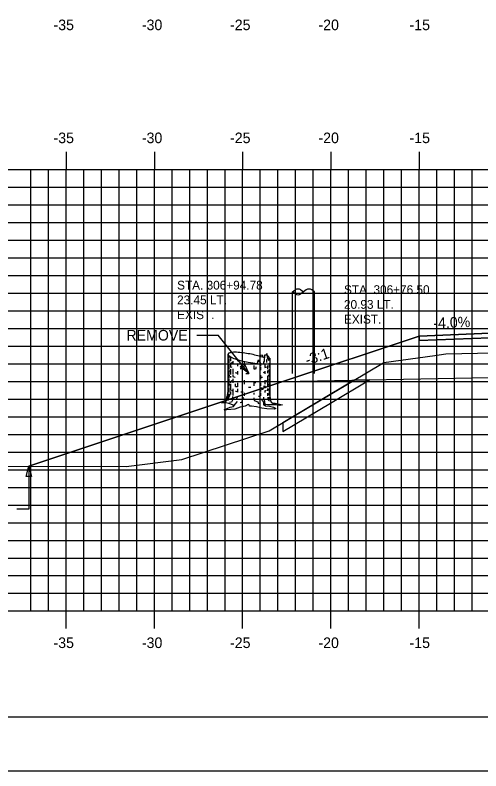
# Model space of a CAD drawing. Extents: x 1137654 to 1137824, y 608981 to 609091.
# Drawn here: x 1137699.51 to 1137725.91, y 608981.28 to 609024.09 of the extents above; entities that cross this region are included whole.
import ezdxf

# ---------------------------------------------------------------- set-up
doc = ezdxf.new("R2010")
doc.units = 0
for name, color, linetype in [('ANNOTATION', 7, 'Continuous'), ('BORDER', 7, 'Continuous'), ('D_Roadway_Edge_Shoulder', 7, 'Continuous'), ('D_Roadway_SlopeLines', 7, 'Continuous'), ('D_Roadway_SubGrade', 7, 'Continuous'), ('D_Text_Monospaced', 7, 'Continuous'), ('D_Text_Standard', 7, 'Continuous'), ('H_V ANNOTATION', 7, 'Continuous'), ('MAJOR', 7, 'Continuous'), ('MINOR', 7, 'Continuous'), ('PLOT BOUNDARY', 7, 'Continuous'), ('S_Roadway_Centerline', 7, 'Continuous'), ('S_Trees_Decid_Pay', 7, 'Continuous'), ('S_Utilities_Pole_Power', 7, 'Continuous'), ('SHADING', 7, 'Continuous')]:
    doc.layers.add(name, color=color, linetype=linetype)

msp = doc.modelspace()

# ---------------------------------------------------------------- linework, layer by layer
msp.add_lwpolyline([(1137700.29, 608998.532), (1137711.685, 609002.33), (1137714.685, 609003.33), (1137722.408, 609005.904), (1137722.409, 609005.904), (1137726.409, 609006.064), (1137737.409, 609006.284), (1137748.409, 609006.504), (1137752.409, 609006.344), (1137760.133, 609003.77), (1137763.133, 609002.77), (1137763.471, 609002.657)])
at = {"layer": 'ANNOTATION'}
for p in [(1137709.813, 609005.955), (1137712.756, 609003.786)]:
    msp.add_line(p, (1137711.013, 609005.955), dxfattribs=at)
msp.add_lwpolyline([(1137712.497, 609004.348), (1137712.756, 609003.786), (1137712.263, 609004.16)], close=True, dxfattribs=at)
at = {"layer": 'BORDER'}
msp.add_lwpolyline([(1137662.41, 608984.335), (1137822.41, 608984.335), (1137822.41, 609089.335), (1137662.41, 609089.335)], close=True, dxfattribs=at)
at = {"layer": 'D_Roadway_Edge_Shoulder'}
msp.add_lwpolyline([(1137726.409, 609006.064), (1137722.409, 609005.904), (1137722.409, 609005.654), (1137726.409, 609005.814)], close=True, dxfattribs=at)
at = {"layer": 'D_Roadway_SlopeLines'}
for points in [[(1137714.685, 609003.33), (1137711.685, 609002.33)], [(1137714.685, 609000.999), (1137714.685, 609000.499), (1137717.38, 609002.105), (1137719.599, 609003.428)], [(1137711.685, 609002.33), (1137700.29, 608998.532)]]:
    msp.add_lwpolyline(points, dxfattribs=at)
at = {"layer": 'D_Roadway_SubGrade'}
msp.add_lwpolyline([(1137726.409, 609005.648), (1137726.409, 609005.814), (1137722.409, 609005.654), (1137722.409, 609005.904), (1137722.408, 609005.904), (1137714.685, 609003.33), (1137726.409, 609003.564)], close=True, dxfattribs=at)
at = {"layer": 'D_Text_Standard'}
msp.add_lwpolyline([(1137700.29, 608998.532), (1137700.3, 608996.105), (1137699.62, 608996.105)], dxfattribs=at)
msp.add_lwpolyline([(1137700.29, 608998.532), (1137700.438, 608997.95), (1137700.147, 608997.949)], close=True, dxfattribs=at)
at = {"layer": 'MAJOR'}
for p, q in [((1137702.409, 609016.337), (1137702.409, 609015.335)), ((1137707.409, 609016.337), (1137707.409, 609015.335)), ((1137712.409, 609016.337), (1137712.409, 609015.335)), ((1137717.409, 609016.337), (1137717.409, 609015.335)), ((1137722.409, 609016.337), (1137722.409, 609015.335)), ((1137667.409, 609015.335), (1137807.409, 609015.335)), ((1137667.409, 609015.335), (1137807.409, 609015.335)), ((1137702.409, 608990.335), (1137702.409, 609015.335)), ((1137707.409, 608990.335), (1137707.409, 609015.335)), ((1137712.409, 608990.335), (1137712.409, 609015.335)), ((1137717.409, 608990.335), (1137717.409, 609015.335)), ((1137722.409, 608990.335), (1137722.409, 609015.335)), ((1137667.409, 609010.335), (1137807.409, 609010.335)), ((1137667.409, 609005.335), (1137807.409, 609005.335)), ((1137667.409, 609000.335), (1137807.409, 609000.335)), ((1137667.409, 608995.335), (1137807.409, 608995.335)), ((1137667.409, 608990.335), (1137807.409, 608990.335)), ((1137667.409, 608990.335), (1137807.409, 608990.335)), ((1137702.409, 608989.333), (1137702.409, 608990.335)), ((1137707.409, 608989.333), (1137707.409, 608990.335)), ((1137712.409, 608989.333), (1137712.409, 608990.335)), ((1137717.409, 608989.333), (1137717.409, 608990.335)), ((1137722.409, 608989.333), (1137722.409, 608990.335))]:
    msp.add_line(p, q, dxfattribs=at)
at = {"layer": 'MINOR'}
for p, q in [((1137700.409, 608990.335), (1137700.409, 609015.335)), ((1137701.409, 608990.335), (1137701.409, 609015.335)), ((1137703.409, 608990.335), (1137703.409, 609015.335)), ((1137704.409, 608990.335), (1137704.409, 609015.335)), ((1137705.409, 608990.335), (1137705.409, 609015.335)), ((1137706.409, 608990.335), (1137706.409, 609015.335)), ((1137708.409, 608990.335), (1137708.409, 609015.335)), ((1137709.409, 608990.335), (1137709.409, 609015.335)), ((1137710.409, 608990.335), (1137710.409, 609015.335)), ((1137711.409, 608990.335), (1137711.409, 609015.335)), ((1137713.409, 608990.335), (1137713.409, 609015.335)), ((1137714.409, 608990.335), (1137714.409, 609015.335)), ((1137715.409, 608990.335), (1137715.409, 609015.335)), ((1137716.409, 608990.335), (1137716.409, 609015.335)), ((1137718.409, 608990.335), (1137718.409, 609015.335)), ((1137719.409, 608990.335), (1137719.409, 609015.335)), ((1137720.409, 608990.335), (1137720.409, 609015.335)), ((1137721.409, 608990.335), (1137721.409, 609015.335)), ((1137723.409, 608990.335), (1137723.409, 609015.335)), ((1137724.409, 608990.335), (1137724.409, 609015.335)), ((1137725.409, 608990.335), (1137725.409, 609015.335)), ((1137667.409, 609014.335), (1137807.409, 609014.335)), ((1137667.409, 609013.335), (1137807.409, 609013.335)), ((1137667.409, 609012.335), (1137807.409, 609012.335)), ((1137667.409, 609011.335), (1137807.409, 609011.335)), ((1137667.409, 609009.335), (1137807.409, 609009.335)), ((1137667.409, 609008.335), (1137807.409, 609008.335)), ((1137667.409, 609007.335), (1137807.409, 609007.335)), ((1137667.409, 609006.335), (1137807.409, 609006.335)), ((1137667.409, 609004.335), (1137807.409, 609004.335)), ((1137667.409, 609003.335), (1137807.409, 609003.335)), ((1137667.409, 609002.335), (1137807.409, 609002.335)), ((1137667.409, 609001.335), (1137807.409, 609001.335)), ((1137667.409, 608999.335), (1137807.409, 608999.335)), ((1137667.409, 608998.335), (1137807.409, 608998.335)), ((1137667.409, 608997.335), (1137807.409, 608997.335)), ((1137667.409, 608996.335), (1137807.409, 608996.335)), ((1137667.409, 608994.335), (1137807.409, 608994.335)), ((1137667.409, 608993.335), (1137807.409, 608993.335)), ((1137667.409, 608992.335), (1137807.409, 608992.335)), ((1137667.409, 608991.335), (1137807.409, 608991.335))]:
    msp.add_line(p, q, dxfattribs=at)
at = {"layer": 'PLOT BOUNDARY'}
msp.add_lwpolyline([(1137654.316, 608981.276), (1137824.316, 608981.276), (1137824.316, 609091.276), (1137654.316, 609091.276)], close=True, dxfattribs=at)
at = {"layer": 'S_Roadway_Centerline'}
msp.add_lwpolyline([(1137667.409, 608999.427), (1137671.375, 608999.533), (1137682.176, 608998.539), (1137682.929, 608998.559), (1137705.808, 608998.523), (1137708.965, 608998.916), (1137713.914, 609000.539), (1137720.407, 609004.41), (1137723.296, 609004.805), (1137723.932, 609004.904), (1137726.625, 609004.961), (1137735.098, 609005.026), (1137742.791, 609004.952), (1137745.524, 609004.989), (1137745.621, 609004.875), (1137747.251, 609004.35), (1137748.161, 609004.238), (1137757.699, 609001.458), (1137758.717, 609001.317), (1137759.74, 609001.407), (1137760.775, 609001.568), (1137762.91, 609002.502), (1137768.911, 609004.157)], dxfattribs=at)
at = {"layer": 'S_Trees_Decid_Pay'}
for p, q in [((1137711.632, 609004.785), (1137711.632, 609004.664)), ((1137711.712, 609004.74), (1137711.712, 609004.487)), ((1137711.632, 609004.612), (1137711.632, 609004.398)), ((1137711.632, 609004.353), (1137711.632, 609004.015)), ((1137711.712, 609004.391), (1137711.712, 609004.127)), ((1137711.845, 609004.487), (1137711.845, 609004.295)), ((1137712.117, 609004.574), (1137712.117, 609004.487)), ((1137712.117, 609004.346), (1137712.117, 609004.207)), ((1137712.5, 609004.473), (1137712.5, 609004.192)), ((1137713.411, 609004.335), (1137713.411, 609004.215)), ((1137713.672, 609004.333), (1137713.672, 609004.128)), ((1137713.757, 609004.581), (1137713.757, 609004.407)), ((1137713.906, 609004.381), (1137713.906, 609004.127)), ((1137711.632, 609003.898), (1137711.632, 609003.538)), ((1137711.712, 609004.03), (1137711.712, 609003.721)), ((1137711.845, 609004.044), (1137711.845, 609003.767)), ((1137712.117, 609003.921), (1137712.117, 609003.729)), ((1137712.5, 609004.127), (1137712.5, 609004.024)), ((1137713.046, 609004.236), (1137713.046, 609004.056)), ((1137713.173, 609004.063), (1137713.168, 609004.17)), ((1137713.411, 609004.164), (1137713.411, 609003.978)), ((1137713.672, 609003.921), (1137713.672, 609003.767)), ((1137713.82, 609004.236), (1137713.82, 609004.024)), ((1137713.82, 609003.958), (1137713.82, 609003.81)), ((1137713.906, 609004.03), (1137713.906, 609003.56)), ((1137711.632, 609003.501), (1137711.632, 609003.052)), ((1137711.712, 609003.633), (1137711.712, 609003.566)), ((1137711.845, 609003.721), (1137711.845, 609003.612)), ((1137711.845, 609003.478), (1137711.845, 609003.249)), ((1137713.411, 609003.692), (1137713.411, 609003.464)), ((1137713.82, 609003.633), (1137713.82, 609003.332)), ((1137713.906, 609003.509), (1137713.906, 609003.375)), ((1137711.712, 609003.332), (1137711.712, 609003.235)), ((1137711.712, 609003.184), (1137711.712, 609002.824)), ((1137712.117, 609003.249), (1137712.117, 609003.041)), ((1137712.5, 609003.412), (1137712.5, 609003.192)), ((1137713.046, 609003.278), (1137713.046, 609003.081)), ((1137713.411, 609003.266), (1137713.411, 609003.081)), ((1137713.672, 609003.404), (1137713.672, 609003.184)), ((1137713.672, 609003.084), (1137713.672, 609002.963)), ((1137713.82, 609003.295), (1137713.82, 609003.052)), ((1137713.906, 609003.318), (1137713.906, 609002.992)), ((1137711.632, 609002.986), (1137711.632, 609002.704)), ((1137711.712, 609002.772), (1137711.712, 609002.605)), ((1137711.845, 609002.92), (1137711.845, 609002.537)), ((1137712.117, 609002.92), (1137712.117, 609002.721)), ((1137712.5, 609002.692), (1137712.5, 609002.518)), ((1137713.046, 609002.698), (1137713.046, 609002.595)), ((1137713.411, 609002.846), (1137713.411, 609002.769)), ((1137713.411, 609002.692), (1137713.411, 609002.518)), ((1137713.672, 609002.812), (1137713.672, 609002.714)), ((1137713.82, 609002.941), (1137713.82, 609002.801)), ((1137713.82, 609002.669), (1137713.82, 609002.513)), ((1137713.906, 609002.963), (1137713.906, 609002.543)), ((1137712.122, 609002.463), (1137712.042, 609002.331)), ((1137713.903, 609002.44), (1137713.918, 609002.323))]:
    msp.add_line(p, q, dxfattribs=at)
for points in [[(1137713.957, 609004.656), (1137713.957, 609002.518), (1137713.977, 609002.377), (1137713.983, 609002.251), (1137714.026, 609002.164), (1137714.119, 609002.115), (1137714.255, 609002.115), (1137714.498, 609002.059), (1137714.665, 609002.01), (1137714.522, 609001.979), (1137714.286, 609002.017), (1137714.076, 609002.004), (1137713.814, 609002.01), (1137713.69, 609002.028), (1137713.66, 609001.986), (1137713.598, 609002.028), (1137713.697, 609001.961), (1137713.932, 609001.936), (1137714.162, 609001.874), (1137714.292, 609001.804), (1137714.193, 609001.761), (1137713.771, 609001.78), (1137713.493, 609001.823), (1137713.194, 609001.899), (1137712.908, 609001.936), (1137712.803, 609001.936), (1137712.785, 609002.017), (1137712.717, 609002.022), (1137712.55, 609001.936), (1137712.264, 609001.88), (1137711.965, 609001.773), (1137711.506, 609001.724), (1137711.352, 609001.736), (1137711.694, 609001.887), (1137711.897, 609001.917), (1137711.885, 609001.992), (1137711.626, 609002.091), (1137711.45, 609002.122), (1137711.21, 609002.133), (1137711.408, 609002.171), (1137711.469, 609002.207), (1137711.494, 609002.294), (1137711.506, 609002.463), (1137711.551, 609002.549), (1137711.58, 609002.79), (1137711.58, 609004.876)], [(1137713.578, 609004.694), (1137713.557, 609004.802), (1137713.425, 609004.833), (1137713.418, 609004.745)], [(1137713.601, 609004.328), (1137713.608, 609004.473), (1137713.654, 609004.465), (1137713.668, 609004.839), (1137713.763, 609004.847), (1137713.777, 609004.927), (1137713.814, 609004.59), (1137713.86, 609004.685), (1137713.88, 609004.53), (1137713.957, 609004.656), (1137713.951, 609004.466)], [(1137713.957, 609004.656), (1137713.911, 609004.679), (1137713.889, 609004.744), (1137713.837, 609004.767), (1137713.803, 609004.692)], [(1137713.439, 609004.333), (1137713.402, 609004.436), (1137713.337, 609004.442), (1137713.337, 609004.524), (1137713.263, 609004.53), (1137713.238, 609004.35)], [(1137712.003, 609003.055), (1137712.005, 609003.132), (1137712.013, 609003.198)], [(1137711.63, 609002.632), (1137711.57, 609002.471), (1137711.556, 609002.346), (1137711.564, 609002.249)], [(1137713.549, 609002.963), (1137713.557, 609002.889), (1137713.483, 609002.883), (1137713.469, 609003)], [(1137711.687, 609002.551), (1137711.616, 609002.448), (1137711.616, 609002.323)], [(1137711.828, 609002.477), (1137711.828, 609002.272), (1137711.77, 609002.162), (1137711.673, 609002.146)], [(1137711.897, 609001.917), (1137711.984, 609002.059), (1137712.116, 609002.202)], [(1137712.482, 609002.403), (1137712.379, 609002.352), (1137712.365, 609002.146), (1137712.262, 609002.117)], [(1137713.048, 609002.412), (1137713.065, 609002.257), (1137713.263, 609002.177), (1137713.308, 609002.074)], [(1137713.5, 609002.276), (1137713.574, 609002.207), (1137713.592, 609002.109), (1137713.598, 609002.028)], [(1137713.69, 609002.028), (1137713.672, 609002.207), (1137713.61, 609002.344), (1137713.617, 609002.444)], [(1137713.837, 609002.448), (1137713.843, 609002.323), (1137713.925, 609002.228)]]:
    msp.add_lwpolyline(points, dxfattribs=at)
for centre, radius, start, end in [((1137711.626, 609004.876), 0.0467, 169.2221, 180.9043), ((1137711.634, 609004.876), 0.0544, 180.9043, 191.7221), ((1137711.626, 609004.876), 0.0467, 157.54, 169.2221), ((1137711.644, 609004.878), 0.0645, 191.7221, 204.3989), ((1137711.633, 609004.873), 0.0544, 146.7221, 157.54), ((1137711.683, 609004.896), 0.107, 204.3989, 214.2221), ((1137711.642, 609004.868), 0.0645, 134.0453, 146.7221), ((1137711.73, 609004.928), 0.164, 214.2221, 228.4286), ((1137711.671, 609004.837), 0.107, 124.2221, 134.0453), ((1137711.703, 609004.79), 0.164, 110.0157, 124.2221), ((1137711.939, 609005.164), 0.48, 228.4286, 236.7221), ((1137711.811, 609004.494), 0.48, 101.7221, 110.0157), ((1137712.389, 609005.85), 1.299, 236.7221, 252.1387), ((1137711.978, 609003.691), 1.299, 86.3056, 101.7221), ((1137711.667, 608998.875), 6.126, 79.2221, 86.3056), ((1137711.667, 608998.875), 6.126, 72.1387, 79.2221), ((1137711.634, 609004.55), 0.0554, 191.6815, 202.5), ((1137711.643, 609004.554), 0.0657, 202.5, 215.1737), ((1137711.679, 609004.579), 0.109, 215.1737, 225), ((1137711.719, 609004.619), 0.166, 225, 238.33), ((1137712.191, 609005.638), 1.292, 250.9084, 254.4349), ((1137713.869, 609010.443), 6.126, 252.1387, 259.2221), ((1137712.767, 609010.226), 5.916, 263.6913, 265.0485), ((1137713.869, 609010.443), 6.126, 259.2221, 264.0853), ((1137713.869, 609010.443), 6.126, 265.9754, 266.3056), ((1137713.558, 609005.627), 1.299, 266.3056, 271.8711), ((1137713.147, 609003.468), 1.299, 66.6931, 72.1387), ((1137711.635, 609004.289), 0.0554, 191.6815, 202.5), ((1137711.644, 609004.293), 0.0657, 202.5, 215.1737), ((1137711.68, 609004.318), 0.109, 215.1737, 225), ((1137711.72, 609004.358), 0.166, 225, 239.1924), ((1137711.72, 609004.095), 0.166, 238.3999, 239.1924), ((1137711.883, 609004.631), 0.484, 239.1924, 242.5838), ((1137711.883, 609004.368), 0.484, 239.1924, 247.5), ((1137712.192, 609005.378), 1.292, 247.5, 251.9171), ((1137712.192, 609005.114), 1.292, 247.5, 248.1929), ((1137712.768, 609009.966), 5.916, 265.1076, 266.4618), ((1137712.768, 609009.966), 5.916, 272.6957, 273.9224), ((1137713.344, 609005.378), 1.292, 284.7144, 289.3881), ((1137713.344, 609005.114), 1.292, 291.6463, 292.5), ((1137713.653, 609004.368), 0.484, 292.5, 300.8076), ((1137713.816, 609004.358), 0.166, 300.8076, 315), ((1137713.816, 609004.095), 0.166, 300.8076, 302.9622), ((1137713.856, 609004.318), 0.109, 315, 324.8263), ((1137713.892, 609004.293), 0.0657, 324.8263, 337.5), ((1137713.901, 609004.289), 0.0554, 337.5, 348.3185), ((1137713.909, 609004.287), 0.0476, 348.3185, 0), ((1137711.635, 609003.768), 0.0554, 191.6815, 202.5), ((1137711.635, 609003.511), 0.0554, 191.6815, 202.5), ((1137711.644, 609003.772), 0.0657, 202.5, 215.1737), ((1137711.644, 609003.514), 0.0657, 202.5, 215.1737), ((1137711.68, 609003.797), 0.109, 215.1737, 225), ((1137711.68, 609003.539), 0.109, 215.1737, 225), ((1137711.72, 609003.837), 0.166, 225, 239.1924), ((1137711.72, 609003.58), 0.166, 225, 237.9306), ((1137711.883, 609004.11), 0.484, 239.1924, 245.3628), ((1137712.192, 609004.857), 1.292, 254.3895, 260.7435), ((1137712.192, 609005.114), 1.292, 261.6338, 262.8454), ((1137712.768, 609009.702), 5.916, 262.8454, 263.6816), ((1137712.768, 609009.702), 5.916, 268.2292, 269.8838), ((1137712.768, 609009.445), 5.916, 276.2405, 277.1546), ((1137713.344, 609004.857), 1.292, 277.1546, 278.1274), ((1137713.344, 609005.114), 1.292, 280.7368, 284.7144), ((1137713.344, 609004.857), 1.292, 291.5158, 292.5), ((1137713.653, 609004.11), 0.484, 294.2275, 300.8076), ((1137713.816, 609003.837), 0.166, 300.8076, 315), ((1137713.816, 609003.58), 0.166, 300.8076, 315), ((1137713.856, 609003.797), 0.109, 315, 324.8263), ((1137713.856, 609003.539), 0.109, 315, 324.8263), ((1137713.892, 609003.772), 0.0657, 324.8263, 337.5), ((1137713.892, 609003.514), 0.0657, 324.8263, 337.5), ((1137713.901, 609003.768), 0.0554, 337.5, 348.3185), ((1137713.901, 609003.511), 0.0554, 337.5, 348.3185), ((1137713.909, 609003.766), 0.0476, 348.3185, 0), ((1137713.909, 609003.509), 0.0476, 348.3185, 0), ((1137711.635, 609003.245), 0.0554, 191.6815, 202.5), ((1137711.72, 609003.314), 0.166, 237.9306, 239.1924), ((1137711.883, 609003.587), 0.484, 239.1924, 247.5), ((1137712.192, 609004.599), 1.292, 249.8999, 254.3895), ((1137712.192, 609004.334), 1.292, 261.6205, 262.8454), ((1137712.768, 609008.922), 5.916, 262.8454, 263.6816), ((1137712.768, 609009.187), 5.916, 272.6957, 273.7279), ((1137713.344, 609004.334), 1.292, 280.7537, 284.7144), ((1137713.344, 609004.599), 1.292, 288.201, 292.5), ((1137713.344, 609004.334), 1.292, 291.6463, 292.5), ((1137713.653, 609003.587), 0.484, 292.5, 300.8076), ((1137713.816, 609003.314), 0.166, 300.8076, 315), ((1137713.856, 609003.274), 0.109, 315, 324.8263), ((1137713.892, 609003.249), 0.0657, 324.8263, 337.5), ((1137713.901, 609003.245), 0.0554, 337.5, 348.3185), ((1137713.909, 609003.243), 0.0476, 348.3185, 0), ((1137711.635, 609002.973), 0.0554, 191.6815, 202.5), ((1137711.644, 609002.977), 0.0657, 202.5, 215.1737), ((1137711.68, 609003.002), 0.109, 215.1737, 225), ((1137711.72, 609003.043), 0.166, 225, 237.9306), ((1137711.883, 609003.058), 0.484, 243.4501, 247.5), ((1137712.183, 609003.808), 1.292, 247.9396, 248.6304), ((1137712.192, 609004.062), 1.292, 250.8466, 254.3895), ((1137712.192, 609004.062), 1.292, 261.6338, 262.8454), ((1137712.768, 609008.65), 5.916, 262.8454, 263.6816), ((1137712.768, 609008.65), 5.916, 265.539, 266.7363), ((1137712.768, 609008.922), 5.916, 269.7243, 270), ((1137712.768, 609008.922), 5.916, 270, 271.0793), ((1137713.344, 609004.062), 1.292, 284.7144, 288.6336), ((1137713.344, 609003.805), 1.292, 291.6463, 292.5), ((1137713.653, 609003.316), 0.484, 292.5, 297.266), ((1137713.653, 609003.058), 0.484, 292.5, 300.8076), ((1137713.816, 609002.785), 0.166, 300.8076, 315), ((1137713.856, 609002.745), 0.109, 315, 324.8263), ((1137713.892, 609002.72), 0.0657, 324.8263, 337.5), ((1137713.901, 609002.716), 0.0554, 337.5, 348.3185), ((1137713.909, 609002.714), 0.0476, 348.3185, 0), ((1137712.768, 609008.392), 5.916, 275.2344, 276.2169)]:
    msp.add_arc(centre, radius, start, end, dxfattribs=at)
at = {"layer": 'S_Utilities_Pole_Power'}
for p, q in [((1137715.234, 609008.407), (1137715.39, 609008.517)), ((1137715.234, 609003.788), (1137715.237, 609008.407)), ((1137715.39, 609008.296), (1137715.234, 609008.407)), ((1137715.702, 609008.517), (1137715.859, 609008.407)), ((1137715.859, 609008.407), (1137715.702, 609008.296)), ((1137716.015, 609008.517), (1137715.859, 609008.407)), ((1137716.484, 609008.407), (1137716.328, 609008.517)), ((1137716.484, 609003.788), (1137716.487, 609008.407))]:
    msp.add_line(p, q, dxfattribs=at)
for centre, start, end in [((1137715.546, 609008.297), 90, 125.2644), ((1137715.546, 609008.518), 234.7356, 270), ((1137715.546, 609008.297), 54.7356, 90), ((1137715.546, 609008.518), 270, 305.2644), ((1137716.171, 609008.297), 90, 125.2644), ((1137716.171, 609008.297), 54.7356, 90)]:
    msp.add_arc(centre, 0.271, start, end, dxfattribs=at)
at = {"layer": 'SHADING'}
for p, q in [((1137718.731, 609003.411), (1137714.685, 609000.999)), ((1137719.599, 609003.428), (1137718.731, 609003.411))]:
    msp.add_line(p, q, dxfattribs=at)
msp.add_lwpolyline([(1137714.685, 609000.999), (1137714.685, 609000.499), (1137717.38, 609002.105), (1137719.599, 609003.428)], dxfattribs=at)

# ---------------------------------------------------------------- texts
at = {"layer": 'ANNOTATION'}
for s, rotation, p in [('-4.0%', 2.2906, (1137723.225, 609006.338)), ('-3:1', 18.4348, (1137716.064, 609004.244))]:
    msp.add_text(s, height=0.6, rotation=rotation, dxfattribs=at).set_placement(p)
msp.add_text('REMOVE', height=0.6, dxfattribs=at).set_placement((1137705.821, 609005.655))
at = {"layer": 'D_Text_Monospaced'}
for s, height, p in [('STA. 306+94.78', 0.49998, (1137708.694, 609008.54)), ('STA. 306+76.50', 0.49998, (1137718.151, 609008.286)), ('23.45 LT.', 0.5, (1137708.694, 609007.706)), ('20.93 LT.', 0.5, (1137718.151, 609007.452)), ('EXIST. ', 0.5, (1137708.694, 609006.866)), ('EXIST. ', 0.5, (1137718.151, 609006.612))]:
    msp.add_text(s, height=height, dxfattribs=at).set_placement(p)
at = {"layer": 'H_V ANNOTATION'}
for s, p in [('-35', (1137701.69, 609023.235)), ('-30', (1137706.698, 609023.235)), ('-25', (1137711.695, 609023.235)), ('-20', (1137716.703, 609023.235)), ('-15', (1137721.866, 609023.235)), ('-35', (1137701.69, 609016.835)), ('-30', (1137706.698, 609016.835)), ('-25', (1137711.695, 609016.835)), ('-20', (1137716.703, 609016.835)), ('-15', (1137721.866, 609016.835)), ('-35', (1137701.69, 608988.235)), ('-30', (1137706.698, 608988.235)), ('-25', (1137711.695, 608988.235)), ('-20', (1137716.703, 608988.235)), ('-15', (1137721.866, 608988.235))]:
    msp.add_text(s, height=0.6, dxfattribs=at).set_placement(p)

doc.saveas('drawing.dxf')
